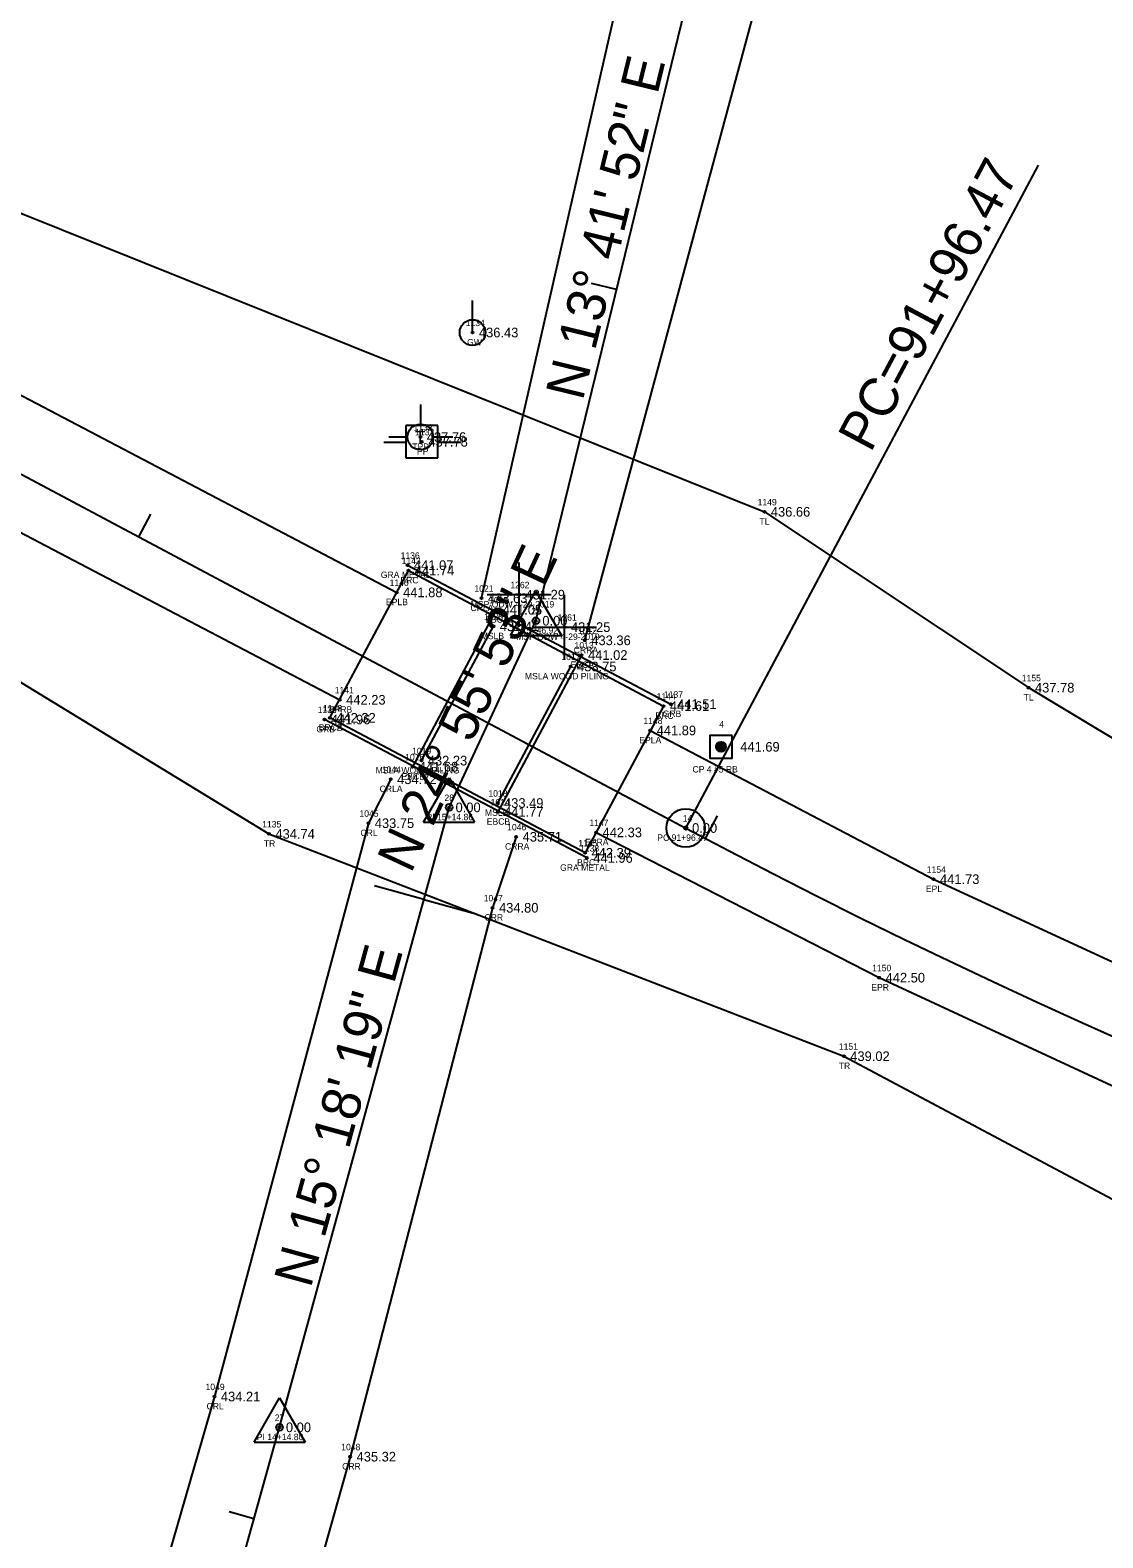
# Model space of a CAD drawing. Extents: x 1809463 to 1812121, y 790645 to 791946.
# Drawn here: x 1810711.3 to 1810878.4, y 791157.1 to 791391.9 of the extents above; entities that cross this region are included whole.
import ezdxf

# ---------------------------------------------------------------- set-up
doc = ezdxf.new("R2010")
doc.units = 0
for name, color, linetype in [('RD_EX_Bridge', 7, 'Continuous'), ('RD_EX_Bridge_txCode', 7, 'Continuous'), ('RD_EX_GuardRail', 7, 'Continuous'), ('RD_EX_GuardRail_txCode', 7, 'Continuous'), ('RD_EX_H2O', 7, 'Continuous'), ('RD_EX_H2O_txCode', 7, 'Continuous'), ('RD_EX_Misc', 7, 'Continuous'), ('RD_EX_Misc_txCode', 7, 'Continuous'), ('RD_EX_Road', 7, 'Continuous'), ('RD_EX_Road_txCode', 7, 'Continuous'), ('RD_EX_TX_Bridge_ELEV', 7, 'Continuous'), ('RD_EX_TX_GuardRail_ELEV', 7, 'Continuous'), ('RD_EX_TX_H2O_ELEV', 7, 'Continuous'), ('RD_EX_TX_Misc_ELEV', 7, 'Continuous'), ('RD_EX_TX_Road_ELEV', 7, 'Continuous'), ('RD_EX_TX_UT_ELEV', 7, 'Continuous'), ('RD_EX_TX_VEG_ELEV', 7, 'Continuous'), ('RD_EX_UT', 7, 'Continuous'), ('RD_EX_UT_txCode', 7, 'Continuous'), ('RD_EX_VEG', 7, 'Continuous'), ('RD_EX_VEG_txCode', 7, 'Continuous'), ('RD_HC_Cl', 7, 'Continuous'), ('RD_HC_Data', 7, 'Continuous'), ('RD_HC_Data_Tic', 7, 'Continuous'), ('RD_HC_Survey', 7, 'Continuous'), ('RD_HC_Survey_ELEV', 7, 'Continuous'), ('RD_HC_Survey_txCode', 7, 'Continuous'), ('RD_HC_txCode', 7, 'Continuous'), ('RD_SMD_Locator', 7, 'Continuous')]:
    doc.layers.add(name, color=color, linetype=linetype)

msp = doc.modelspace()

# ---------------------------------------------------------------- linework, layer by layer
at = {"layer": 'RD_EX_Bridge'}
for p, q in [((1810783.91, 791301.62), (1810770.85, 791277.19)), ((1810797.2, 791294.58), (1810784.13, 791270.16))]:
    msp.add_line(p, q, dxfattribs=at)
msp.add_lwpolyline([(1810758, 791284.81), (1810770.23, 791307.73), (1810809.94, 791286.64), (1810797.74, 791263.79), (1810758, 791284.81)], dxfattribs=at)
at = {"layer": 'RD_EX_GuardRail'}
for p, q in [((1810770.09, 791308.57), (1810811.07, 791286.94)), ((1810798.02, 791262.99), (1810757.16, 791284.54))]:
    msp.add_line(p, q, dxfattribs=at)
at = {"layer": 'RD_EX_H2O'}
for p, q in [((1810787.47, 791298.98), (1810787.47, 791308.98)), ((1810782.47, 791303.98), (1810792.47, 791303.98)), ((1810794.54, 791293.93), (1810794.54, 791303.93)), ((1810789.54, 791298.93), (1810799.54, 791298.93))]:
    msp.add_line(p, q, dxfattribs=at)
for points in [[(1810797.71, 791296.87), (1810832.51, 791426.19), (1810824.93, 791438.48), (1810774.65, 791454.91), (1810754.82, 791471.31), (1810756.82, 791503.13), (1810738.07, 791600.2), (1810752.73, 791691.4), (1810775.78, 791733), (1810786.04, 791774.85), (1810772.38, 791809.33)], [(1810781.61, 791303.43), (1810807.2, 791415.78), (1810808.22, 791420.49), (1810765.69, 791434.41), (1810731.68, 791459.26), (1810725.69, 791486.37), (1810718.09, 791596.36), (1810712.45, 791605.3), (1810726.19, 791694.57), (1810745.89, 791743.36), (1810754.16, 791771.51), (1810757.05, 791789.67), (1810743.21, 791805.43)], [(1810767.47, 791275.24), (1810763.99, 791268.4), (1810740.03, 791179.13), (1810709.69, 791074.11), (1810683.47, 790982.07), (1810621.06, 790917.07), (1810544.86, 790829.8)], [(1810787.01, 791266.28), (1810783.34, 791255.23), (1810761.16, 791169.77), (1810733.17, 791070.34), (1810716.3, 790997.73)]]:
    msp.add_lwpolyline(points, dxfattribs=at)
for centre in [(1810787.47, 791303.98), (1810794.54, 791298.93)]:
    msp.add_circle(centre, 0.15, dxfattribs=at)
at = {"layer": 'RD_EX_Misc'}
for p, q in [((1810772.25, 791278.14), (1810783.46, 791299.05)), ((1810795.49, 791292.79), (1810784.12, 791271.54))]:
    msp.add_line(p, q, dxfattribs=at)
at = {"layer": 'RD_EX_Road'}
for points in [[(1810147.3, 791633.32), (1810235.73, 791586.37), (1810316.89, 791542.45), (1810324.32, 791538.42), (1810350.04, 791524.6), (1810412.94, 791490.75), (1810461.45, 791466.07), (1810501.18, 791444.55), (1810589.18, 791397.37), (1810679.08, 791351.18), (1810768.4, 791304.34)], [(1810138.18, 791616.8), (1810226.92, 791569.59), (1810315.11, 791521.87), (1810404.37, 791475.11), (1810492.73, 791428.56), (1810580.86, 791380.55), (1810670.21, 791334.43), (1810759.54, 791287.61)], [(1810807.88, 791282.84), (1810852, 791259.68), (1810897.52, 791238.67), (1810942.78, 791219.24), (1810989.92, 791202.01), (1811037.03, 791187.9), (1811084.94, 791176.28), (1811134.78, 791167.28), (1811183.92, 791161.02), (1811232.9, 791156.58), (1811282.68, 791154.92), (1811285.25, 791154.67), (1811313.54, 791153.96), (1811332.83, 791153.68), (1811383.78, 791152.53), (1811433.81, 791151.61), (1811483.97, 791148.18)], [(1810799.46, 791266.97), (1810843.53, 791244.35), (1810889.8, 791222.88), (1810936.32, 791202.72), (1810983.79, 791185.28), (1811031.51, 791170.21), (1811081.62, 791158.02), (1811131.99, 791148.92), (1811148.3, 791146.24), (1811177.02, 791142.75), (1811182.52, 791142.23), (1811232.71, 791137.62), (1811281.86, 791136.25), (1811332.25, 791135.72), (1811383.92, 791134.19), (1811422.24, 791132.82), (1811433.21, 791132.2), (1811452.43, 791131.25), (1811482.29, 791129.59)]]:
    msp.add_lwpolyline(points, dxfattribs=at)
at = {"layer": 'RD_EX_UT'}
for p, q in [((1810780.21, 791344.79), (1810780.21, 791349.79)), ((1810772.09, 791333.59), (1810772.09, 791330.52)), ((1810774.83, 791330.3), (1810769.83, 791330.3)), ((1810769.83, 791330.3), (1810769.83, 791325.3)), ((1810774.83, 791325.3), (1810774.83, 791330.3)), ((1810766.4, 791327.74), (1810769.87, 791327.74)), ((1810767.16, 791328.53), (1810770.09, 791328.53)), ((1810774.09, 791328.53), (1810777.16, 791328.53)), ((1810774.76, 791327.74), (1810778.4, 791327.74)), ((1810769.83, 791325.3), (1810774.83, 791325.3))]:
    msp.add_line(p, q, dxfattribs=at)
for centre in [(1810780.21, 791344.79), (1810772.09, 791328.52)]:
    msp.add_circle(centre, 2, dxfattribs=at)
at = {"layer": 'RD_EX_VEG'}
for points in [[(1810130.25, 791598.81), (1810215.39, 791551.2), (1810300.2, 791497.21), (1810388.33, 791446.45), (1810482.97, 791410.13), (1810570.21, 791358.18), (1810662.04, 791319.54), (1810748.52, 791266.73), (1810838.03, 791232.12), (1810883.83, 791207.75), (1810930.73, 791188.17), (1810978.23, 791166.26), (1811026.78, 791154.63), (1811075.78, 791136.08), (1811111.46, 791120.38), (1811106.22, 791101.92)], [(1810341.02, 791567.09), (1810359.88, 791551.99), (1810422.51, 791511.77), (1810509.88, 791459.82), (1810597.87, 791416.6), (1810690.3, 791371.23), (1810825.66, 791316.88), (1810866.79, 791289.5), (1810909.83, 791263.61), (1810951.77, 791236.76), (1810996.45, 791220.63), (1811044.92, 791210.53), (1811089.45, 791196.27), (1811139.01, 791190.33), (1811186.69, 791184.29), (1811236.76, 791180.63), (1811249.82, 791178.89), (1811262.54, 791198.89)]]:
    msp.add_lwpolyline(points, dxfattribs=at)
at = {"layer": 'RD_HC_Cl'}
for p, q in [((1810106.46, 791644.15), (1810813.4, 791267.65)), ((1810790.08, 791299.92), (1810819.85, 791422.06)), ((1810776.57, 791270.86), (1810790.08, 791299.92)), ((1810750.16, 791174.34), (1810776.57, 791270.86)), ((1810721.56, 791071.88), (1810750.16, 791174.34))]:
    msp.add_line(p, q, dxfattribs=at)
msp.add_arc((1811303.09, 792187.12), 1041.74, 241.96114, 268.76562, dxfattribs=at)
at = {"layer": 'RD_HC_Data'}
for p, q in [((1810813.4, 791267.65), (1810868.36, 791370.86)), ((1810786.11, 791297.63), (1810790.08, 791304.51)), ((1810790.08, 791304.51), (1810794.05, 791297.63)), ((1810786.11, 791297.63), (1810794.05, 791297.63)), ((1810772.6, 791268.56), (1810776.57, 791275.44)), ((1810776.57, 791275.44), (1810780.54, 791268.56)), ((1810772.6, 791268.56), (1810780.54, 791268.56)), ((1810746.19, 791172.05), (1810750.16, 791178.93)), ((1810750.16, 791178.93), (1810754.13, 791172.05)), ((1810746.19, 791172.05), (1810754.13, 791172.05))]:
    msp.add_line(p, q, dxfattribs=at)
for centre, radius in [((1810790.08, 791299.92), 0.529), ((1810776.57, 791270.86), 0.529), ((1810813.4, 791267.65), 3), ((1810813.4, 791267.65), 0.282), ((1810750.16, 791174.34), 0.529)]:
    msp.add_circle(centre, radius, dxfattribs=at)
at = {"layer": 'RD_HC_Data_Tic'}
for p, q in [((1810802.65, 791351.5), (1810798.76, 791352.45)), ((1810728.25, 791313), (1810730.13, 791316.53)), ((1810816.51, 791265.99), (1810818.38, 791269.53)), ((1810772.65, 791256.52), (1810764.93, 791258.63)), ((1810772.65, 791256.52), (1810780.36, 791254.41)), ((1810746.18, 791160.09), (1810742.33, 791161.16))]:
    msp.add_line(p, q, dxfattribs=at)
at = {"layer": 'RD_HC_Survey'}
for p, q in [((1810818.15, 791280.12), (1810818.15, 791280.47)), ((1810818.18, 791280.03), (1810818.18, 791280.56)), ((1810818.2, 791279.97), (1810818.2, 791280.62)), ((1810818.23, 791279.92), (1810818.23, 791280.67)), ((1810818.25, 791279.88), (1810818.25, 791280.71)), ((1810818.28, 791279.85), (1810818.28, 791280.74)), ((1810818.3, 791279.81), (1810818.3, 791280.78)), ((1810818.33, 791279.78), (1810818.33, 791280.81)), ((1810818.35, 791279.76), (1810818.35, 791280.83)), ((1810818.38, 791279.73), (1810818.38, 791280.86)), ((1810818.4, 791279.71), (1810818.4, 791280.88)), ((1810818.43, 791279.69), (1810818.43, 791280.9)), ((1810818.45, 791279.67), (1810818.45, 791280.92)), ((1810818.48, 791279.65), (1810818.48, 791280.94)), ((1810818.5, 791279.64), (1810818.5, 791280.95)), ((1810818.53, 791279.62), (1810818.53, 791280.97)), ((1810818.55, 791279.61), (1810818.55, 791280.98)), ((1810818.57, 791279.6), (1810818.57, 791280.99)), ((1810818.6, 791279.59), (1810818.6, 791281)), ((1810818.62, 791279.58), (1810818.62, 791281.01)), ((1810818.65, 791279.57), (1810818.65, 791281.02)), ((1810818.67, 791279.56), (1810818.67, 791281.03)), ((1810818.7, 791279.55), (1810818.7, 791281.04)), ((1810818.72, 791279.55), (1810818.72, 791281.04)), ((1810818.75, 791279.54), (1810818.75, 791281.05)), ((1810818.77, 791279.54), (1810818.77, 791281.05)), ((1810818.8, 791279.53), (1810818.8, 791281.06)), ((1810818.82, 791279.53), (1810818.82, 791281.06)), ((1810818.85, 791279.53), (1810818.85, 791281.06)), ((1810818.87, 791279.53), (1810818.87, 791281.06)), ((1810818.9, 791279.53), (1810818.9, 791281.06)), ((1810818.92, 791279.53), (1810818.92, 791281.06)), ((1810818.95, 791279.53), (1810818.95, 791281.06)), ((1810818.97, 791279.53), (1810818.97, 791281.06)), ((1810819, 791279.53), (1810819, 791281.06)), ((1810819.02, 791279.53), (1810819.02, 791281.06)), ((1810819.05, 791279.54), (1810819.05, 791281.05)), ((1810819.07, 791279.54), (1810819.07, 791281.05)), ((1810819.09, 791279.55), (1810819.09, 791281.04)), ((1810819.12, 791279.56), (1810819.12, 791281.03)), ((1810819.14, 791279.56), (1810819.14, 791281.03)), ((1810819.17, 791279.57), (1810819.17, 791281.02)), ((1810819.19, 791279.58), (1810819.19, 791281.01)), ((1810819.22, 791279.59), (1810819.22, 791281)), ((1810819.24, 791279.6), (1810819.24, 791280.98)), ((1810819.27, 791279.62), (1810819.27, 791280.97)), ((1810819.29, 791279.63), (1810819.29, 791280.96)), ((1810819.32, 791279.65), (1810819.32, 791280.94)), ((1810819.34, 791279.66), (1810819.34, 791280.93)), ((1810819.37, 791279.68), (1810819.37, 791280.91)), ((1810819.39, 791279.7), (1810819.39, 791280.89)), ((1810819.42, 791279.72), (1810819.42, 791280.87)), ((1810819.44, 791279.75), (1810819.44, 791280.84)), ((1810819.47, 791279.77), (1810819.47, 791280.82)), ((1810819.49, 791279.8), (1810819.49, 791280.79)), ((1810819.52, 791279.83), (1810819.52, 791280.76)), ((1810819.54, 791279.86), (1810819.54, 791280.73)), ((1810819.56, 791279.9), (1810819.56, 791280.69)), ((1810819.59, 791279.95), (1810819.59, 791280.64)), ((1810819.61, 791280), (1810819.61, 791280.59)), ((1810819.64, 791280.07), (1810819.64, 791280.52)), ((1810819.66, 791280.18), (1810819.66, 791280.41))]:
    msp.add_line(p, q, dxfattribs=at)
msp.add_lwpolyline([(1810820.65, 791282.04), (1810817.15, 791282.04), (1810817.15, 791278.54), (1810820.65, 791278.54)], close=True, dxfattribs=at)
msp.add_circle((1810818.9, 791280.29), 0.769, dxfattribs=at)
at = {"layer": 'RD_SMD_Locator'}
for centre in [(1810780.21, 791344.79), (1810772.09, 791328.52), (1810772.34, 791327.79), (1810825.66, 791316.88), (1810770.09, 791308.57), (1810770.23, 791307.73), (1810768.4, 791304.34), (1810781.61, 791303.43), (1810783.91, 791301.62), (1810783.46, 791299.05), (1810790.08, 791299.92), (1810797.71, 791296.87), (1810797.2, 791294.58), (1810795.49, 791292.79), (1810866.79, 791289.5), (1810759.54, 791287.61), (1810811.07, 791286.94), (1810758, 791284.81), (1810758, 791284.81), (1810809.94, 791286.64), (1810757.16, 791284.54), (1810807.88, 791282.84), (1810818.9, 791280.29), (1810772.25, 791278.14), (1810767.47, 791275.24), (1810770.85, 791277.19), (1810776.57, 791270.86), (1810784.12, 791271.54), (1810763.99, 791268.4), (1810784.13, 791270.16), (1810748.52, 791266.73), (1810787.01, 791266.28), (1810799.46, 791266.97), (1810813.4, 791267.65), (1810797.74, 791263.79), (1810798.02, 791262.99), (1810852, 791259.68), (1810783.34, 791255.23), (1810843.53, 791244.35), (1810838.03, 791232.12), (1810740.03, 791179.13), (1810750.16, 791174.34), (1810761.16, 791169.77)]:
    msp.add_circle(centre, 0.15, dxfattribs=at)

# ---------------------------------------------------------------- texts
at = {"layer": 'RD_EX_Bridge_txCode'}
for s, p in [('1143', (1810769.17, 791308.73)), ('BRC', (1810768.98, 791305.73)), ('1015', (1810782.8, 791302.62)), ('EBCA', (1810782.19, 791299.62)), ('1013', (1810796.1, 791295.58)), ('EBCA', (1810795.49, 791292.58)), ('1144', (1810808.88, 791287.64)), ('1146', (1810756.91, 791285.81)), ('1142', (1810756.93, 791285.81)), ('BRC', (1810808.69, 791284.64)), ('BRCA', (1810756.26, 791282.81)), ('BRCB', (1810756.27, 791282.81)), ('1016', (1810769.72, 791278.19)), ('EBCB', (1810769.15, 791275.19)), ('1014', (1810783.03, 791271.16)), ('EBCB', (1810782.43, 791268.16)), ('1145', (1810796.68, 791264.79)), ('BRC', (1810796.49, 791261.79))]:
    msp.add_text(s, height=1, dxfattribs=at).set_placement(p)
at = {"layer": 'RD_EX_GuardRail_txCode'}
for s, p in [('1136', (1810769.01, 791309.57)), ('GRA METAL', (1810765.93, 791306.57)), ('1137', (1810810.01, 791287.94)), ('1139', (1810756.1, 791285.54)), ('GRB', (1810809.82, 791284.94)), ('GRB', (1810755.91, 791282.54)), ('1138', (1810796.95, 791263.99)), ('GRA METAL', (1810793.85, 791260.99))]:
    msp.add_text(s, height=1, dxfattribs=at).set_placement(p)
at = {"layer": 'RD_EX_H2O_txCode'}
for s, p in [('1262', (1810786.1, 791304.98)), ('1021', (1810780.5, 791304.43)), ('CRLA', (1810779.89, 791301.43)), ('MSP ODW 4-29-2019', (1810779.93, 791301.98)), ('1261', (1810793.46, 791299.93)), ('1012', (1810796.6, 791297.87)), ('MSP ODW 4-29-2019', (1810787.01, 791296.93)), ('CRRA', (1810795.97, 791294.87)), ('1044', (1810766.08, 791276.24)), ('CRLA', (1810765.75, 791273.24)), ('1045', (1810762.6, 791269.4)), ('1046', (1810785.6, 791267.28)), ('CRL', (1810762.76, 791266.4)), ('CRRA', (1810785.27, 791264.28)), ('1047', (1810781.95, 791256.23)), ('CRR', (1810782.08, 791253.23)), ('1049', (1810738.64, 791180.13)), ('CRL', (1810738.8, 791177.13)), ('1048', (1810759.77, 791170.77)), ('CRR', (1810759.91, 791167.77))]:
    msp.add_text(s, height=1, dxfattribs=at).set_placement(p)
at = {"layer": 'RD_EX_Misc_txCode'}
for s, p in [('1020', (1810782, 791300.05)), ('MSLB', (1810781.49, 791297.05)), ('1017', (1810794.05, 791293.79)), ('MSLA WOOD PILING', (1810788.37, 791290.79)), ('1019', (1810770.8, 791279.14)), ('MSLA WOOD PILING', (1810765.12, 791276.14)), ('1018', (1810782.68, 791272.54)), ('MSLB', (1810782.15, 791269.54))]:
    msp.add_text(s, height=1, dxfattribs=at).set_placement(p)
at = {"layer": 'RD_EX_Road_txCode'}
for s, p in [('1140', (1810767.3, 791305.34)), ('EPLB', (1810766.73, 791302.34)), ('1141', (1810758.76, 791288.61)), ('EPRB', (1810757.84, 791285.61)), ('1148', (1810806.81, 791283.84)), ('EPLA', (1810806.18, 791280.84)), ('1147', (1810798.4, 791267.97)), ('EPRA', (1810797.74, 791264.97)), ('1154', (1810850.94, 791260.68)), ('EPL', (1810850.8, 791257.68)), ('1150', (1810842.43, 791245.35)), ('EPR', (1810842.3, 791242.35))]:
    msp.add_text(s, height=1, dxfattribs=at).set_placement(p)
at = {"layer": 'RD_EX_TX_Bridge_ELEV'}
for s, p in [('441.74', (1810771.23, 791306.98)), ('441.05', (1810784.91, 791300.87)), ('441.02', (1810798.2, 791293.83)), ('441.61', (1810810.94, 791285.89)), ('442.32', (1810759, 791284.06)), ('442.32', (1810759, 791284.06)), ('441.68', (1810771.85, 791276.44)), ('441.77', (1810785.13, 791269.41)), ('442.39', (1810798.74, 791263.04))]:
    msp.add_text(s, height=1.5, dxfattribs=at).set_placement(p)
at = {"layer": 'RD_EX_TX_GuardRail_ELEV'}
for s, p in [('441.07', (1810771.09, 791307.82)), ('441.51', (1810812.07, 791286.19)), ('441.96', (1810758.16, 791283.79)), ('441.96', (1810799.02, 791262.24))]:
    msp.add_text(s, height=1.5, dxfattribs=at).set_placement(p)
at = {"layer": 'RD_EX_TX_H2O_ELEV'}
for s, p in [('433.63', (1810782.61, 791302.68)), ('433.36', (1810798.71, 791296.12)), ('434.72', (1810768.47, 791274.49)), ('433.75', (1810764.99, 791267.65)), ('435.71', (1810788.01, 791265.53)), ('434.80', (1810784.34, 791254.48)), ('434.21', (1810741.03, 791178.38)), ('435.32', (1810762.16, 791169.02))]:
    msp.add_text(s, height=1.5, dxfattribs=at).set_placement(p)
at = {"layer": 'RD_EX_TX_Misc_ELEV'}
for s, p in [('431.29', (1810788.47, 791303.23)), ('431.41', (1810784.46, 791298.3)), ('431.25', (1810795.54, 791298.18)), ('433.75', (1810796.49, 791292.04)), ('432.23', (1810773.25, 791277.39)), ('433.49', (1810785.12, 791270.79))]:
    msp.add_text(s, height=1.5, dxfattribs=at).set_placement(p)
at = {"layer": 'RD_EX_TX_Road_ELEV'}
for s, p in [('441.88', (1810769.4, 791303.59)), ('442.23', (1810760.54, 791286.86)), ('441.89', (1810808.88, 791282.09)), ('442.33', (1810800.46, 791266.22)), ('441.73', (1810853, 791258.93)), ('442.50', (1810844.53, 791243.6))]:
    msp.add_text(s, height=1.5, dxfattribs=at).set_placement(p)
at = {"layer": 'RD_EX_TX_UT_ELEV'}
for s, p in [('436.43', (1810781.21, 791344.04)), ('437.76', (1810773.09, 791327.77))]:
    msp.add_text(s, height=1.5, dxfattribs=at).set_placement(p)
at = {"layer": 'RD_EX_TX_VEG_ELEV'}
for s, p in [('436.66', (1810826.66, 791316.13)), ('437.78', (1810867.79, 791288.75)), ('434.74', (1810749.52, 791265.98)), ('439.02', (1810839.03, 791231.37))]:
    msp.add_text(s, height=1.5, dxfattribs=at).set_placement(p)
at = {"layer": 'RD_EX_UT'}
msp.add_text('T', height=2, dxfattribs=at).set_placement((1810771.24, 791327.47))
at = {"layer": 'RD_EX_UT_txCode'}
for s, p in [('1134', (1810779.15, 791345.79)), ('GW', (1810779.37, 791342.79)), ('1133', (1810771.03, 791329.52)), ('1132', (1810771.28, 791328.79)), ('TPP', (1810770.83, 791326.52)), ('PP', (1810771.56, 791325.79))]:
    msp.add_text(s, height=1, dxfattribs=at).set_placement(p)
at = {"layer": 'RD_EX_VEG_txCode'}
for s, p in [('1149', (1810824.6, 791317.88)), ('TL', (1810824.89, 791314.88)), ('1155', (1810865.73, 791290.5)), ('TL', (1810866.02, 791287.5)), ('1135', (1810747.46, 791267.73)), ('TR', (1810747.72, 791264.73)), ('1151', (1810837.25, 791233.12)), ('TR', (1810837.24, 791230.12))]:
    msp.add_text(s, height=1, dxfattribs=at).set_placement(p)
at = {"layer": 'RD_HC_Data'}
for s, rotation, p in [('N 13%%d 41\' 52" E', 76.3021, (1810797.37, 791334.04)), ('PC=91+96.47', 61.9611, (1810842.19, 791325.96)), ('N 24%%d 55\' 53" E', 65.0687, (1810770.62, 791260.44)), ('N 15%%d 18\' 19" E', 74.6948, (1810755.01, 791195.88))]:
    msp.add_text(s, height=6, rotation=rotation, dxfattribs=at).set_placement(p)
at = {"layer": 'RD_HC_Survey_ELEV'}
for s, p in [('437.78', (1810773.34, 791327.04)), ('0.00', (1810791.08, 791299.17)), ('441.69', (1810821.9, 791279.54)), ('0.00', (1810777.57, 791270.11)), ('0.00', (1810814.4, 791266.9)), ('0.00', (1810751.16, 791173.59))]:
    msp.add_text(s, height=1.5, dxfattribs=at).set_placement(p)
at = {"layer": 'RD_HC_Survey_txCode'}
for s, p in [('4', (1810818.62, 791283.29)), ('CP 4 #5 RB', (1810814.46, 791276.29))]:
    msp.add_text(s, height=1, dxfattribs=at).set_placement(p)
at = {"layer": 'RD_HC_txCode'}
for s, p in [('29', (1810789.35, 791300.92)), ('PI 15+46.92', (1810786.28, 791297.92)), ('28', (1810775.84, 791271.86)), ('PI 15+14.86', (1810773.05, 791268.86)), ('14', (1810812.95, 791268.65)), ('PC 91+96.47', (1810808.98, 791265.65)), ('27', (1810749.42, 791175.34)), ('PI 14+14.80', (1810746.62, 791172.34))]:
    msp.add_text(s, height=1, dxfattribs=at).set_placement(p)

doc.saveas('drawing.dxf')
